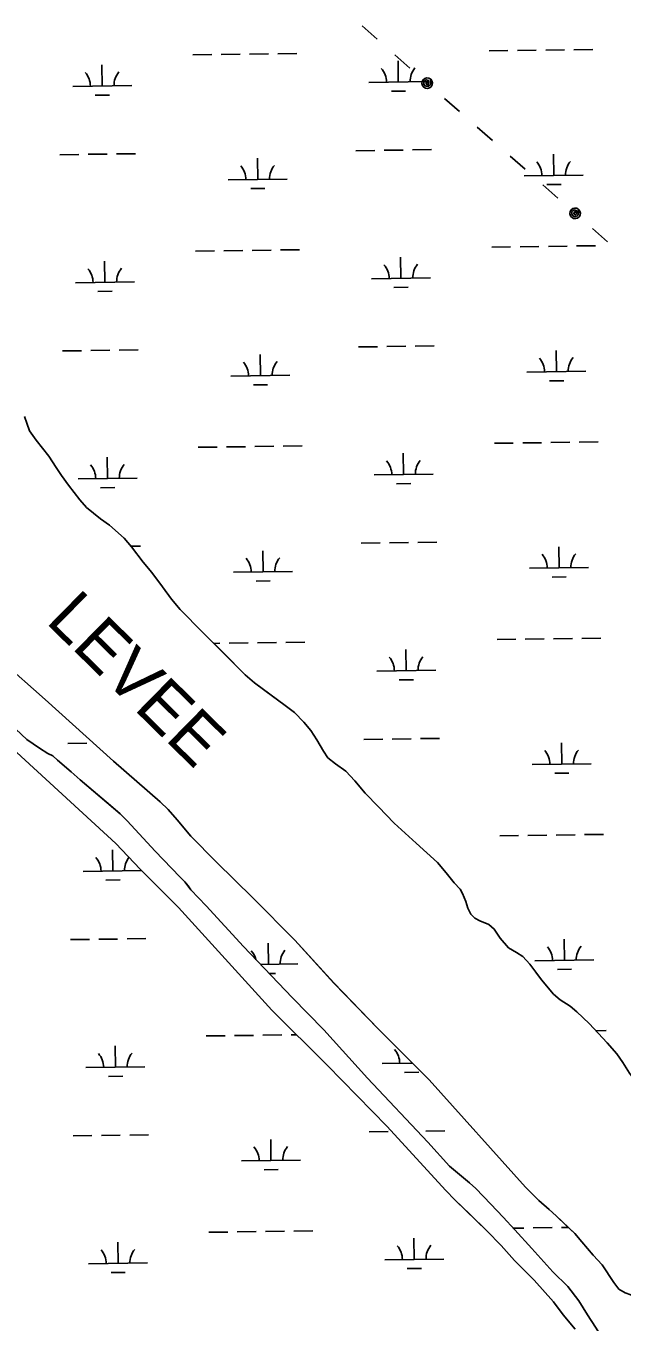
# Model space of a CAD drawing. Extents: x 3753511 to 3791668, y 379550 to 405377.
# Drawn here: x 3782224 to 3783234, y 387781 to 389978 of the extents above; entities that cross this region are included whole.
import ezdxf

# ---------------------------------------------------------------- set-up
doc = ezdxf.new("R2010")
doc.units = 0
for name, color, linetype in [('V-RIVR-IDEN', 7, 'Continuous'), ('V-TOPO-SHOR', 7, 'Continuous'), ('V-UTIL-LINE', 7, 'Continuous'), ('V-WETL-SWMP', 7, 'Continuous')]:
    doc.layers.add(name, color=color, linetype=linetype)

msp = doc.modelspace()

# ---------------------------------------------------------------- linework, layer by layer
at = {"layer": 'V-TOPO-SHOR'}
for points in [[(3782221.7, 389316.1), (3782225.2, 389305), (3782230.2, 389292), (3782241.5, 389276.2), (3782262.5, 389249.2), (3782275.4, 389229.8), (3782284.3, 389216), (3782296, 389199.8), (3782315.5, 389174.8), (3782326.8, 389162.1), (3782350.2, 389142.6), (3782365.5, 389131.9), (3782390.5, 389109.7), (3782403, 389095.4), (3782422.9, 389069.2), (3782437.3, 389051.8), (3782455.2, 389027.3), (3782470.8, 389006.3), (3782485.2, 388989.2), (3782523.8, 388950), (3782558.6, 388915.4), (3782595.7, 388878.5), (3782611.3, 388864.6), (3782631.3, 388849.9), (3782663.4, 388826.4), (3782679.4, 388814.1), (3782695, 388798.2), (3782706.7, 388784), (3782716.8, 388767.8), (3782728.1, 388748.8), (3782735.9, 388737.3), (3782748.4, 388727.4), (3782766, 388715), (3782781.2, 388698.7)], [(3782178.3, 388905.6), (3782182.7, 388901.7), (3782256.7, 388836.6), (3782372.4, 388731.9), (3782451.2, 388662.7), (3782465.1, 388649.8), (3782480.2, 388632.4), (3782503.2, 388605), (3782546.6, 388561), (3782609, 388499.6), (3782679.7, 388428.5), (3782746, 388355.8), (3782820.7, 388278.3), (3782907.4, 388191.5), (3783070.6, 388009.7)], [(3781980.3, 388844.6), (3782013, 388855.5), (3782019.5, 388859), (3782026.6, 388862.6), (3782033.8, 388865.3), (3782041.1, 388867.4), (3782046.2, 388867.7), (3782051.3, 388867.5), (3782054.2, 388866.7), (3782066.3, 388863.5), (3782077.6, 388857.9), (3782104.8, 388837.5), (3782151.2, 388798.5), (3782222.6, 388733.4), (3782376.5, 388592.1), (3782417.3, 388548.8), (3782482.6, 388484.1), (3782555.9, 388403.2), (3782640.6, 388310), (3782734.3, 388216.4), (3782836.1, 388112.8), (3782934.9, 388004.6)], [(3782177.3, 388813), (3782225.7, 388768.8), (3782247, 388754), (3782261.3, 388744.9), (3782269.5, 388740.7), (3782277.3, 388733.3), (3782300.6, 388713.7), (3782315.8, 388700.2), (3782367.4, 388656.7), (3782383.8, 388642.8), (3782395.3, 388630.7), (3782442.9, 388579.2), (3782484.6, 388535.8), (3782493.4, 388527.2), (3782498.7, 388520.5), (3782503.7, 388514), (3782529.5, 388486.6), (3782592.5, 388417.9), (3782675.4, 388331.1), (3782728.6, 388276.7), (3782803.1, 388194.3), (3782905.1, 388085.9), (3782941.7, 388045.1), (3782975.9, 388017.2)], [(3782781.2, 388698.7), (3782799.1, 388677.7), (3782821.4, 388654.3)], [(3782821.4, 388654.3), (3782847.9, 388626.6), (3782885.1, 388592.8), (3782921.4, 388560.3), (3782936.2, 388542.8), (3782949.9, 388525.4), (3782960, 388514.7), (3782963.9, 388507.6), (3782969.7, 388494.1), (3782973.1, 388482.7), (3782977.8, 388472.4), (3782984.8, 388465.7), (3782993.4, 388461.3), (3783008.7, 388454.9), (3783017.7, 388447.3), (3783027.8, 388431.9), (3783041.9, 388415.6), (3783055.6, 388407.6), (3783066.1, 388400.5), (3783078.2, 388387.8), (3783088.4, 388374.3), (3783092.6, 388368), (3783098.5, 388360.9), (3783103.2, 388354.5), (3783118.4, 388336.7), (3783129.7, 388327.1), (3783146.6, 388316.4), (3783157.9, 388306.8)], [(3783157.9, 388306.8), (3783178.6, 388287), (3783209, 388254.5), (3783225.4, 388235.5), (3783235.9, 388220.8), (3783246.8, 388203), (3783258.9, 388187.2), (3783275.2, 388167.8), (3783303.4, 388140.4), (3783336.6, 388111.8), (3783365.1, 388089.5), (3783376.5, 388079.6), (3783389.8, 388065.7), (3783397.5, 388052.2), (3783401, 388044.3), (3783405.3, 388035.6), (3783416.9, 388017.3)], [(3783270.4, 387783.5), (3783258.9, 387762.9), (3783249.4, 387752.5), (3783240.5, 387742.9), (3783229.6, 387738), (3783222, 387737.9), (3783216.5, 387739.9), (3783202.8, 387750.8), (3783189.6, 387772.6), (3783175.7, 387793.1), (3783161.1, 387817), (3783142.4, 387841.5), (3783116.9, 387866), (3783081.6, 387905.5), (3783052.6, 387937.5), (3783032.6, 387958.7), (3783011.8, 387981.1), (3782986.3, 388007.7), (3782975.9, 388017.2)], [(3782934.9, 388004.6), (3782951.5, 387987.5), (3782976.3, 387963.7), (3783005.3, 387935.8), (3783029.5, 387910.6), (3783052.3, 387885.4), (3783069.6, 387867.7), (3783085.5, 387852.1), (3783118, 387815.3), (3783134.6, 387793.5), (3783154.6, 387769)], [(3783070.6, 388009.7), (3783093.4, 387987.2), (3783110.6, 387971.6), (3783122.4, 387961.4), (3783139.6, 387945), (3783154.1, 387931.4), (3783165.9, 387917.1), (3783185.2, 387894.7), (3783200.4, 387878.3), (3783220.5, 387848.3), (3783228.9, 387836.7), (3783239.9, 387830.6), (3783249.5, 387827.2), (3783259.2, 387819.1), (3783265.4, 387807.5), (3783268.9, 387794.5), (3783270.4, 387783.5)]]:
    msp.add_lwpolyline(points, dxfattribs=at)
at = {"layer": 'V-UTIL-LINE'}
for points in [[(3782793.7, 389978.3), (3782819.3, 389955.8)], [(3782849.3, 389929.4), (3782874.8, 389906.9)], [(3782904.1, 389881.2), (3782904.4, 389884), (3782902.4, 389882.9), (3782902.1, 389880.2), (3782904.5, 389878.5), (3782906.9, 389881), (3782906.7, 389885.6), (3782902.6, 389886.9), (3782898.6, 389884.2), (3782898.6, 389879.6), (3782901.3, 389876), (3782906.1, 389875.9), (3782910, 389879.8), (3782910, 389887.9), (3782907, 389889.7), (3782903.5, 389890.2), (3782900.1, 389889.2), (3782897.3, 389887.1), (3782895.6, 389884.1), (3782895.1, 389880.6), (3782896, 389877.2), (3782898.2, 389874.4), (3782901.2, 389872.7), (3782904.7, 389872.2), (3782908.1, 389873.1), (3782910.9, 389875.2), (3782912.6, 389878.3), (3782913.1, 389881.7), (3782912.2, 389885.1), (3782910, 389887.9)], [(3782933.4, 389855.4), (3782958.9, 389833)], [(3782988.9, 389806.5), (3783014.5, 389784.1)], [(3783044.5, 389757.7), (3783070, 389735.2)], [(3783100.1, 389708.8), (3783125.6, 389686.3)], [(3783154.9, 389660.6), (3783155.2, 389663.4), (3783153.2, 389662.3), (3783152.9, 389659.6), (3783155.3, 389657.9), (3783157.7, 389660.3), (3783157.5, 389665), (3783153.4, 389666.3), (3783149.3, 389663.6), (3783149.4, 389659), (3783152, 389655.4), (3783156.9, 389655.3), (3783160.7, 389659.2), (3783160.8, 389667.3), (3783157.8, 389669.1), (3783154.3, 389669.5), (3783150.9, 389668.6), (3783148.1, 389666.5), (3783146.4, 389663.5), (3783145.9, 389660), (3783146.8, 389656.6), (3783148.9, 389653.8), (3783152, 389652), (3783155.5, 389651.6), (3783158.8, 389652.5), (3783161.6, 389654.6), (3783163.4, 389657.7), (3783163.9, 389661.1), (3783163, 389664.5), (3783160.8, 389667.3)], [(3783184.2, 389634.8), (3783209.7, 389612.3)]]:
    msp.add_lwpolyline(points, dxfattribs=at)
at = {"layer": 'V-WETL-SWMP'}
for p, q in [((3782507.1, 389929.2), (3782539.1, 389929.6)), ((3782555.1, 389929.8), (3782587.1, 389930.3)), ((3782603.1, 389930.5), (3782635.1, 389930.9)), ((3782651.1, 389931.1), (3782683.1, 389931.6)), ((3783009, 389936), (3783041, 389936.4)), ((3783057, 389936.6), (3783089, 389937)), ((3783104.9, 389937.3), (3783136.9, 389937.7)), ((3783152.9, 389937.9), (3783184.9, 389938.3)), ((3782353.2, 389876.4), (3782352.7, 389912.3)), ((3782855.1, 389883.1), (3782854.6, 389919.1)), ((3782805.1, 389882.5), (3782905.1, 389883.8)), ((3782303.2, 389875.7), (3782403.2, 389877)), ((3782341.4, 389860.8), (3782365.4, 389861.1)), ((3782843.3, 389867.5), (3782867.3, 389867.9)), ((3782879.2, 389768), (3782911.2, 389768.5)), ((3782281.4, 389759.9), (3782313.4, 389760.4)), ((3782329.4, 389760.6), (3782361.4, 389761)), ((3782377.4, 389761.2), (3782409.4, 389761.7)), ((3782616.8, 389718), (3782616.3, 389754)), ((3782783.2, 389766.7), (3782815.2, 389767.2)), ((3782831.2, 389767.4), (3782863.2, 389767.8)), ((3783118.7, 389724.8), (3783118.2, 389760.8)), ((3783068.7, 389724.2), (3783168.7, 389725.5)), ((3782566.8, 389717.4), (3782666.8, 389718.7)), ((3782605, 389702.4), (3782629, 389702.8)), ((3783106.9, 389709.2), (3783130.9, 389709.6)), ((3782511.6, 389596.5), (3782543.6, 389597)), ((3782559.6, 389597.2), (3782591.6, 389597.6)), ((3782607.6, 389597.8), (3782639.6, 389598.3)), ((3782655.6, 389598.5), (3782687.6, 389598.9)), ((3783013.5, 389603.3), (3783045.5, 389603.8)), ((3783061.5, 389604), (3783093.4, 389604.4)), ((3783109.4, 389604.6), (3783141.4, 389605.1)), ((3783157.4, 389605.3), (3783189.4, 389605.7)), ((3782357.7, 389543.7), (3782357.2, 389579.7)), ((3782859.6, 389550.5), (3782859.1, 389586.5)), ((3782809.6, 389549.8), (3782909.6, 389551.2)), ((3782307.7, 389543), (3782407.7, 389544.4)), ((3782345.9, 389528.1), (3782369.9, 389528.4)), ((3782847.8, 389534.9), (3782871.8, 389535.2)), ((3782285.9, 389427.3), (3782317.9, 389427.7)), ((3782333.9, 389427.9), (3782365.9, 389428.4)), ((3782381.9, 389428.6), (3782413.9, 389429)), ((3782621.3, 389385.4), (3782620.8, 389421.4)), ((3782787.7, 389434.1), (3782819.7, 389434.5)), ((3782835.7, 389434.7), (3782867.7, 389435.2)), ((3782883.7, 389435.4), (3782915.7, 389435.8)), ((3783123.2, 389392.2), (3783122.7, 389428.2)), ((3782571.3, 389384.7), (3782671.3, 389386.1)), ((3783073.2, 389391.5), (3783173.2, 389392.9)), ((3783111.4, 389376.6), (3783135.4, 389376.9)), ((3782609.5, 389369.8), (3782633.5, 389370.1)), ((3782225.2, 389305), (3782221.7, 389316.1)), ((3782230.2, 389292), (3782225.2, 389305)), ((3782241.5, 389276.2), (3782230.2, 389292)), ((3782262.5, 389249.2), (3782241.5, 389276.2)), ((3782516.1, 389263.9), (3782548.1, 389264.3)), ((3782564.1, 389264.5), (3782596.1, 389265)), ((3782612.1, 389265.2), (3782644.1, 389265.6)), ((3782660.1, 389265.8), (3782692.1, 389266.3)), ((3783018, 389270.7), (3783050, 389271.1)), ((3783066, 389271.3), (3783097.9, 389271.8)), ((3783113.9, 389272), (3783145.9, 389272.4)), ((3783161.9, 389272.6), (3783193.9, 389273.1)), ((3782275.4, 389229.8), (3782262.5, 389249.2)), ((3782362.2, 389211.1), (3782361.7, 389247.1)), ((3782864.1, 389217.8), (3782863.6, 389253.8)), ((3782284.3, 389216), (3782275.4, 389229.8)), ((3782296, 389199.8), (3782284.3, 389216)), ((3782315.5, 389174.8), (3782296, 389199.8)), ((3782312.2, 389210.4), (3782412.2, 389211.7)), ((3782814.1, 389217.2), (3782914.1, 389218.5)), ((3782852.3, 389202.3), (3782876.3, 389202.6)), ((3782350.4, 389195.5), (3782374.4, 389195.8)), ((3782326.8, 389162.1), (3782315.5, 389174.8)), ((3782350.2, 389142.6), (3782326.8, 389162.1)), ((3782365.5, 389131.9), (3782350.2, 389142.6)), ((3782390.5, 389109.7), (3782365.5, 389131.9)), ((3782403, 389095.4), (3782390.5, 389109.7)), ((3782402.3, 389096.2), (3782418.3, 389096.4)), ((3782422.9, 389069.2), (3782403, 389095.4)), ((3782625.8, 389052.8), (3782625.3, 389088.7)), ((3782792.2, 389101.4), (3782824.2, 389101.9)), ((3782840.2, 389102.1), (3782872.2, 389102.5)), ((3782888.2, 389102.7), (3782920.2, 389103.2)), ((3783127.7, 389059.5), (3783127.2, 389095.5)), ((3782437.3, 389051.8), (3782422.9, 389069.2)), ((3782455.2, 389027.3), (3782437.3, 389051.8)), ((3782575.8, 389052.1), (3782675.8, 389053.4)), ((3783077.7, 389058.9), (3783177.7, 389060.2)), ((3783115.9, 389043.9), (3783139.9, 389044.3)), ((3782470.8, 389006.3), (3782455.2, 389027.3)), ((3782614, 389037.2), (3782638, 389037.5)), ((3782485.2, 388989.2), (3782470.8, 389006.3)), ((3782523.8, 388950), (3782485.2, 388989.2)), ((3782595.7, 388878.5), (3782523.8, 388950)), ((3782664.6, 388933.2), (3782696.6, 388933.6)), ((3783022.5, 388938), (3783054.4, 388938.5)), ((3783070.4, 388938.7), (3783102.4, 388939.1)), ((3783118.4, 388939.3), (3783150.4, 388939.8)), ((3783166.4, 388940), (3783198.4, 388940.4)), ((3782542.4, 388931.5), (3782552.6, 388931.7)), ((3782568.6, 388931.9), (3782600.6, 388932.3)), ((3782616.6, 388932.5), (3782648.6, 388933)), ((3782868.6, 388885.2), (3782868.1, 388921.2)), ((3782611.3, 388864.6), (3782595.7, 388878.5)), ((3782818.6, 388884.5), (3782918.6, 388885.9)), ((3782856.8, 388869.6), (3782880.8, 388869.9)), ((3782663.4, 388826.4), (3782611.3, 388864.6)), ((3782679.4, 388814.1), (3782663.4, 388826.4)), ((3782695, 388798.2), (3782679.4, 388814.1)), ((3782706.7, 388784), (3782695, 388798.2)), ((3782716.8, 388767.8), (3782706.7, 388784)), ((3782294.9, 388762), (3782326.9, 388762.4)), ((3782728.1, 388748.8), (3782716.8, 388767.8)), ((3782796.7, 388768.8), (3782828.7, 388769.2)), ((3782844.7, 388769.4), (3782876.7, 388769.9)), ((3782892.7, 388770.1), (3782924.7, 388770.5)), ((3783132.2, 388726.9), (3783131.7, 388762.9)), ((3782735.9, 388737.3), (3782728.1, 388748.8)), ((3782748.4, 388727.4), (3782735.9, 388737.3)), ((3782222.6, 388733.4), (3782376.5, 388592.1)), ((3782766, 388715), (3782748.4, 388727.4)), ((3782781.2, 388698.7), (3782766, 388715)), ((3783082.2, 388726.2), (3783182.2, 388727.6)), ((3782799.1, 388677.7), (3782781.2, 388698.7)), ((3783120.4, 388711.3), (3783144.4, 388711.6)), ((3782821.4, 388654.3), (3782799.1, 388677.7)), ((3782847.9, 388626.6), (3782821.4, 388654.3)), ((3782885.1, 388592.8), (3782847.9, 388626.6)), ((3783027, 388605.4), (3783058.9, 388605.8)), ((3783074.9, 388606), (3783106.9, 388606.5)), ((3783122.9, 388606.7), (3783154.9, 388607.1)), ((3783170.9, 388607.3), (3783202.9, 388607.8)), ((3782376.5, 388592.1), (3782417.3, 388548.8)), ((3782921.4, 388560.3), (3782885.1, 388592.8)), ((3782371.2, 388545.8), (3782370.7, 388581.8)), ((3782936.2, 388542.8), (3782921.4, 388560.3)), ((3782321.2, 388545.1), (3782419.7, 388546.4)), ((3782417.3, 388548.8), (3782482.6, 388484.1)), ((3782949.9, 388525.4), (3782936.2, 388542.8)), ((3782359.4, 388530.2), (3782383.4, 388530.5)), ((3782960, 388514.7), (3782949.9, 388525.4)), ((3782963.9, 388507.6), (3782960, 388514.7)), ((3782969.7, 388494.1), (3782963.9, 388507.6)), ((3782973.1, 388482.7), (3782969.7, 388494.1)), ((3782482.6, 388484.1), (3782555.9, 388403.2)), ((3782977.8, 388472.4), (3782973.1, 388482.7)), ((3782984.8, 388465.7), (3782977.8, 388472.4)), ((3782993.4, 388461.3), (3782984.8, 388465.7)), ((3783008.7, 388454.9), (3782993.4, 388461.3)), ((3783017.7, 388447.3), (3783008.7, 388454.9)), ((3782299.4, 388429.4), (3782331.4, 388429.8)), ((3782347.4, 388430), (3782379.3, 388430.4)), ((3782395.3, 388430.7), (3782427.3, 388431.1)), ((3783027.8, 388431.9), (3783017.7, 388447.3)), ((3783041.9, 388415.6), (3783027.8, 388431.9)), ((3783136.7, 388394.2), (3783136.2, 388430.2)), ((3782634.8, 388387.5), (3782634.3, 388423.5)), ((3783055.6, 388407.6), (3783041.9, 388415.6)), ((3783066.1, 388400.5), (3783055.6, 388407.6)), ((3782555.9, 388403.2), (3782640.6, 388310)), ((3782621.7, 388387.3), (3782684.8, 388388.1)), ((3783078.2, 388387.8), (3783066.1, 388400.5)), ((3783088.4, 388374.3), (3783078.2, 388387.8)), ((3783086.7, 388393.6), (3783186.7, 388394.9)), ((3782636.2, 388372), (3782647, 388372.2)), ((3783092.6, 388368), (3783088.4, 388374.3)), ((3783098.5, 388360.9), (3783092.6, 388368)), ((3783124.9, 388378.7), (3783148.9, 388379)), ((3783103.2, 388354.5), (3783098.5, 388360.9)), ((3783118.4, 388336.7), (3783103.2, 388354.5)), ((3783129.7, 388327.1), (3783118.4, 388336.7)), ((3783146.6, 388316.4), (3783129.7, 388327.1)), ((3782640.6, 388310), (3782734.3, 388216.4)), ((3783157.9, 388306.8), (3783146.6, 388316.4)), ((3783178.6, 388287), (3783157.9, 388306.8)), ((3783209, 388254.5), (3783178.6, 388287)), ((3783189.9, 388274.9), (3783207.4, 388275.1)), ((3782529.6, 388266), (3782561.6, 388266.4)), ((3782577.6, 388266.6), (3782609.6, 388267)), ((3782625.6, 388267.3), (3782657.6, 388267.7)), ((3782673.6, 388267.9), (3782682.6, 388268)), ((3783225.4, 388235.5), (3783209, 388254.5)), ((3782375.7, 388213.1), (3782375.2, 388249.1)), ((3783235.9, 388220.8), (3783225.4, 388235.5)), ((3782325.7, 388212.5), (3782425.7, 388213.8)), ((3782734.3, 388216.4), (3782836.1, 388112.8)), ((3782827.6, 388219.2), (3782879, 388219.9)), ((3782877.6, 388219.9), (3782877.5, 388221.4)), ((3782363.9, 388197.5), (3782387.9, 388197.9)), ((3782865.8, 388204.3), (3782889.8, 388204.6)), ((3782399.8, 388098), (3782431.8, 388098.4)), ((3782805.7, 388103.5), (3782837.7, 388103.9)), ((3782836.1, 388112.8), (3782934.9, 388004.6)), ((3782901.7, 388104.8), (3782933.7, 388105.2)), ((3782303.9, 388096.7), (3782335.9, 388097.1)), ((3782351.9, 388097.4), (3782383.8, 388097.8)), ((3782639.3, 388054.8), (3782638.8, 388090.8)), ((3782589.3, 388054.1), (3782689.3, 388055.5)), ((3782627.5, 388039.2), (3782651.5, 388039.6)), ((3782934.9, 388004.6), (3782951.5, 387987.5)), ((3782951.5, 387987.5), (3783005.3, 387935.8)), ((3782534.1, 387933.3), (3782566.1, 387933.7)), ((3782582.1, 387934), (3782614.1, 387934.4)), ((3782630.1, 387934.6), (3782662.1, 387935)), ((3782678.1, 387935.3), (3782710.1, 387935.7)), ((3782882.1, 387887.3), (3782881.6, 387923.3)), ((3783005.3, 387935.8), (3783029.5, 387910.6)), ((3783050, 387940.3), (3783067.9, 387940.5)), ((3783083.9, 387940.7), (3783115.9, 387941.2)), ((3783131.9, 387941.4), (3783143.4, 387941.6)), ((3782380.2, 387880.5), (3782379.7, 387916.5)), ((3783029.5, 387910.6), (3783052.3, 387885.4)), ((3782330.2, 387879.8), (3782430.2, 387881.2)), ((3782832.1, 387886.6), (3782932.1, 387887.9)), ((3783052.3, 387885.4), (3783069.6, 387867.7)), ((3782368.4, 387864.9), (3782392.4, 387865.2)), ((3782870.3, 387871.7), (3782894.3, 387872)), ((3783069.6, 387867.7), (3783085.5, 387852.1)), ((3783085.5, 387852.1), (3783118, 387815.3)), ((3783118, 387815.3), (3783134.6, 387793.5)), ((3783134.6, 387793.5), (3783154.6, 387769))]:
    msp.add_line(p, q, dxfattribs=at)
for points in [[(3782182.7, 388901.7), (3782256.7, 388836.6), (3782372.4, 388731.9), (3782451.2, 388662.7), (3782465.1, 388649.8), (3782480.2, 388632.4), (3782503.2, 388605), (3782546.6, 388561), (3782609, 388499.6), (3782679.7, 388428.5), (3782746, 388355.9), (3782820.7, 388278.3), (3782907.4, 388191.5), (3783070.6, 388009.7), (3783093.4, 387987.2), (3783110.6, 387971.6), (3783122.4, 387961.4), (3783154.1, 387931.4), (3783165.9, 387917.1), (3783185.2, 387894.7), (3783200.4, 387878.3), (3783220.5, 387848.3), (3783228.9, 387836.7), (3783239.9, 387830.6)], [(3783189.6, 387772.6), (3783175.7, 387793.1), (3783161.1, 387817), (3783142.4, 387841.5), (3783116.9, 387866), (3783081.6, 387905.5), (3783052.6, 387937.5), (3783032.6, 387958.7), (3783011.8, 387981.1), (3782986.3, 388007.7), (3782975.9, 388017.2), (3782941.7, 388045.1), (3782905.1, 388085.9), (3782803.1, 388194.3), (3782728.6, 388276.7), (3782675.4, 388331.1), (3782592.5, 388417.9), (3782529.5, 388486.6), (3782503.7, 388514), (3782493.4, 388527.2), (3782484.6, 388535.8), (3782442.9, 388579.2), (3782395.3, 388630.7), (3782383.8, 388642.8), (3782315.8, 388700.2), (3782300.6, 388713.7), (3782277.3, 388733.3), (3782269.5, 388740.7), (3782261.3, 388744.9), (3782247, 388754), (3782225.7, 388768.8), (3782177.3, 388813)]]:
    msp.add_lwpolyline(points, dxfattribs=at)
for centre, start, end in [((3782408.4, 389877.6), 140.0029, 181.5465), ((3782799.8, 389882.9), 0.0029, 41.5465), ((3782910.3, 389884.4), 140.0029, 181.5465), ((3782298, 389876.1), 0.0029, 41.5465), ((3783063.4, 389724.6), 0.0029, 41.5465), ((3783173.9, 389726), 140.0029, 181.5465), ((3782561.6, 389717.8), 0.0029, 41.5465), ((3782672, 389719.3), 140.0029, 181.5465), ((3782804.3, 389550.2), 0.0029, 41.5465), ((3782914.8, 389551.7), 140.0029, 181.5465), ((3782302.5, 389543.4), 0.0029, 41.5465), ((3782412.9, 389544.9), 140.0029, 181.5465), ((3782566.1, 389385.1), 0.0029, 41.5465), ((3782676.5, 389386.6), 140.0029, 181.5465), ((3783067.9, 389391.9), 0.0029, 41.5465), ((3783178.4, 389393.4), 140.0029, 181.5465), ((3782808.8, 389217.6), 0.0029, 41.5465), ((3782919.3, 389219.1), 140.0029, 181.5465), ((3782307, 389210.8), 0.0029, 41.5465), ((3782417.4, 389212.3), 140.0029, 181.5465), ((3782570.6, 389052.5), 0.0029, 41.5465), ((3782681, 389054), 140.0029, 181.5465), ((3783072.4, 389059.3), 0.0029, 41.5465), ((3783182.9, 389060.8), 140.0029, 181.5465), ((3782813.3, 388884.9), 0.0029, 41.5465), ((3782923.8, 388886.4), 140.0029, 181.5465), ((3783076.9, 388726.6), 0.0029, 41.5465), ((3783187.4, 388728.1), 140.0029, 181.5465), ((3782316, 388545.5), 0.0029, 41.5465), ((3782426.4, 388547), 142.1019, 181.5465), ((3782579.6, 388387.2), 13.684, 41.5465), ((3782690, 388388.7), 140.0029, 181.5465), ((3783081.4, 388394), 0.0029, 41.5465), ((3783191.9, 388395.5), 140.0029, 181.5465), ((3782320.5, 388212.9), 0.0029, 41.5465), ((3782430.9, 388214.4), 140.0029, 181.5465), ((3782822.3, 388219.6), 0.0029, 41.5465), ((3782584.1, 388054.5), 0.0029, 41.5465), ((3782694.5, 388056), 140.0029, 181.5465), ((3782324.9, 387880.2), 0.0029, 41.5465), ((3782435.4, 387881.7), 140.0029, 181.5465), ((3782826.8, 387887), 0.0029, 41.5465), ((3782937.3, 387888.5), 140.0029, 181.5465)]:
    msp.add_arc(centre, 35.2, start, end, dxfattribs=at)

# ---------------------------------------------------------------- texts
at = {"layer": 'V-RIVR-IDEN'}
msp.add_text('LEVEE', height=83, rotation=315.4897, dxfattribs=at).set_placement((3782255.8, 388967.7))

doc.saveas('drawing.dxf')
